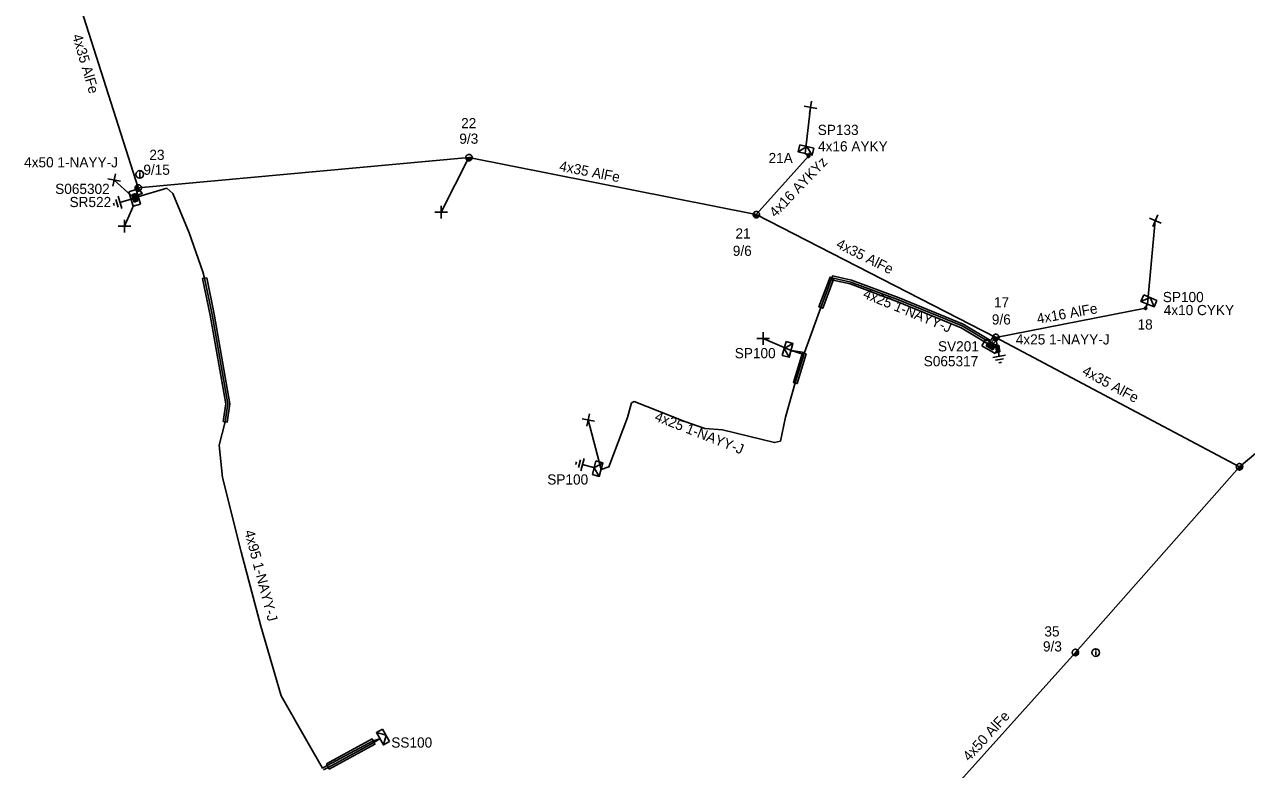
# Model space of a CAD drawing. Extents: x -748492 to -735633, y -1146251 to -1139940.
# Drawn here: x -745823 to -745702.9, y -1143676.6 to -1143603.4 of the extents above; entities that cross this region are included whole.
import ezdxf

# ---------------------------------------------------------------- set-up
doc = ezdxf.new("R2010")
doc.units = 0
for name, color, linetype in [('Vrstva 1', 7, 'Continuous'), ('Vrstva 10', 7, 'Continuous'), ('Vrstva 12', 7, 'Continuous'), ('Vrstva 13', 7, 'Continuous'), ('Vrstva 14', 7, 'Continuous'), ('Vrstva 15', 7, 'Continuous'), ('Vrstva 16', 7, 'Continuous'), ('Vrstva 2', 7, 'Continuous'), ('Vrstva 20', 7, 'Continuous'), ('Vrstva 28', 7, 'Continuous'), ('Vrstva 29', 7, 'Continuous'), ('Vrstva 30', 7, 'Continuous'), ('Vrstva 31', 7, 'Continuous'), ('Vrstva 33', 7, 'Continuous'), ('Vrstva 34', 7, 'Continuous'), ('Vrstva 36', 7, 'Continuous'), ('Vrstva 5', 7, 'Continuous'), ('Vrstva 52', 7, 'Continuous'), ('Vrstva 53', 7, 'Continuous'), ('Vrstva 54', 7, 'Continuous'), ('Vrstva 59', 7, 'Continuous'), ('Vrstva 6', 7, 'Continuous'), ('Vrstva 8', 7, 'Continuous'), ('Vrstva 9', 7, 'Continuous')]:
    doc.layers.add(name, color=color, linetype=linetype)

# ---------------------------------------------------------------- blocks, each defined once
blk = doc.blocks.new('NN440')
at = {"layer": 'Vrstva 2'}
for points in [[(0.63, 0), (0.63, 0.06), (0.62, 0.13), (0.6, 0.19), (0.58, 0.25), (0.55, 0.31), (0.51, 0.37), (0.47, 0.42), (0.42, 0.46), (0.37, 0.51), (0.32, 0.54), (0.26, 0.57), (0.2, 0.59), (0.13, 0.61), (0.07, 0.62), (0, 0.63), (-0.06, 0.62), (-0.13, 0.61), (-0.19, 0.59), (-0.26, 0.57), (-0.31, 0.54), (-0.37, 0.51), (-0.42, 0.46), (-0.47, 0.42), (-0.51, 0.37), (-0.54, 0.31), (-0.57, 0.25), (-0.6, 0.19), (-0.62, 0.13), (-0.63, 0.06), (-0.63, 0), (-0.63, -0.07), (-0.62, -0.14), (-0.6, -0.2), (-0.57, -0.26), (-0.54, -0.32), (-0.51, -0.37), (-0.47, -0.43), (-0.42, -0.47), (-0.37, -0.51), (-0.31, -0.55), (-0.26, -0.58), (-0.19, -0.6), (-0.13, -0.62), (-0.06, -0.63), (0, -0.63), (0.07, -0.63), (0.13, -0.62), (0.2, -0.6), (0.26, -0.58), (0.32, -0.55), (0.37, -0.51), (0.42, -0.47), (0.47, -0.43), (0.51, -0.37), (0.55, -0.32), (0.58, -0.26), (0.6, -0.2), (0.62, -0.14), (0.63, -0.07), (0.63, 0)], [(-0.63, 0), (0.63, 0)], [(-0.6, -0.18), (0.57, -0.18)], [(-0.51, -0.32), (0.5, -0.32)], [(-0.37, -0.47), (0.35, -0.47)]]:
    blk.add_lwpolyline(points, dxfattribs=at)
blk = doc.blocks.new('NN770')
at = {"layer": 'Vrstva 10'}
for p, q in [((0, 0.19), (0, 0.26)), ((0, -0.28), (0, 0.11))]:
    blk.add_line(p, q, dxfattribs=at)
blk.add_circle((0, -0.01), 0.375, dxfattribs=at)
blk = doc.blocks.new('NN800')
at = {"layer": 'Vrstva 1'}
for points in [[(-0.44, 0.44), (0.44, -0.44)], [(-0.44, -0.44), (0.44, 0.44)]]:
    blk.add_lwpolyline(points, dxfattribs=at)
blk = doc.blocks.new('NN820')
at = {"layer": 'Vrstva 13'}
for points in [[(0, 0), (0, -1.05)], [(-0.16, -0.81), (0.16, -0.81)], [(-0.16, -1.47), (-0.16, -0.81)], [(0, -1.05), (-0.06, -0.93)], [(0, -1.05), (0.06, -0.93)], [(0.16, -0.81), (0.16, -1.47)], [(0.16, -1.47), (-0.16, -1.47)], [(0, -1.47), (0, -1.87)]]:
    blk.add_lwpolyline(points, dxfattribs=at)
blk = doc.blocks.new('NN620')
at = {"layer": 'Vrstva 8'}
for points in [[(0.75, 0), (-0.75, 0)], [(-0.75, 0), (-0.75, -0.75)], [(0.75, -0.75), (0.75, 0)], [(-0.75, -0.75), (0.75, -0.75)], [(0.37, -0.18), (-0.38, -0.18)], [(-0.38, -0.18), (-0.38, -0.56)], [(-0.38, -0.56), (0.37, -0.56)], [(0.32, -0.23), (-0.33, -0.23)], [(-0.33, -0.23), (-0.33, -0.51)], [(-0.33, -0.51), (0.32, -0.51)], [(0.27, -0.27), (-0.28, -0.27)], [(-0.28, -0.27), (-0.28, -0.46)], [(-0.28, -0.46), (0.27, -0.46)], [(0.23, -0.32), (-0.23, -0.32)], [(-0.23, -0.32), (-0.23, -0.42)], [(-0.23, -0.42), (0.23, -0.42)], [(-0.19, -0.37), (0.19, -0.37)], [(0.23, -0.42), (0.23, -0.32)], [(0.27, -0.46), (0.27, -0.27)], [(0.32, -0.51), (0.32, -0.23)], [(0.37, -0.56), (0.37, -0.18)]]:
    blk.add_lwpolyline(points, dxfattribs=at)
blk = doc.blocks.new('NN630')
at = {"layer": 'Vrstva 9'}
for points in [[(0, -0.7), (-0.7, 0)], [(-0.7, -0.7), (-0.7, 0), (0.7, 0), (0.7, -0.7)], [(-0.7, -0.7), (0.7, -0.7)], [(0, -0.7), (0.7, 0)]]:
    blk.add_lwpolyline(points, dxfattribs=at)
blk = doc.blocks.new('NN810')
at = {"layer": 'Vrstva 14'}
for points in [[(0, -0.64), (0, -1.89)], [(0.63, -1.89), (-0.62, -1.89)], [(0.39, -2.2), (-0.4, -2.2)], [(0, -2.52), (-0.12, -2.52)], [(0.14, -2.52), (0, -2.52)]]:
    blk.add_lwpolyline(points, dxfattribs=at)
blk = doc.blocks.new('NN500')
at = {"layer": 'Vrstva 2'}
for points in [[(0, -0.24), (0.02, -0.23), (0.05, -0.23), (0.07, -0.22), (0.09, -0.22), (0.12, -0.2), (0.14, -0.19), (0.16, -0.18), (0.17, -0.16), (0.19, -0.14), (0.2, -0.12), (0.21, -0.1), (0.22, -0.07), (0.23, -0.05), (0.23, -0.02), (0.23, 0), (0.23, 0.02), (0.23, 0.05), (0.22, 0.07), (0.21, 0.1), (0.2, 0.12), (0.19, 0.14), (0.17, 0.16), (0.16, 0.17), (0.14, 0.19), (0.12, 0.2), (0.09, 0.21), (0.07, 0.22), (0.05, 0.23), (0.02, 0.23), (0, 0.23), (-0.03, 0.23), (-0.05, 0.23), (-0.07, 0.22), (-0.1, 0.21), (-0.12, 0.2), (-0.14, 0.19), (-0.16, 0.17), (-0.18, 0.16), (-0.19, 0.14), (-0.2, 0.12), (-0.22, 0.1), (-0.22, 0.07), (-0.23, 0.05), (-0.23, 0.02), (-0.24, 0), (-0.23, -0.02), (-0.23, -0.05), (-0.22, -0.07), (-0.22, -0.1), (-0.2, -0.12), (-0.19, -0.14), (-0.18, -0.16), (-0.16, -0.18), (-0.14, -0.19), (-0.12, -0.2), (-0.1, -0.22), (-0.07, -0.22), (-0.05, -0.23), (-0.03, -0.23), (0, -0.24)], [(0, -0.24), (0.02, -0.23), (0.05, -0.23), (0.07, -0.22), (0.09, -0.22), (0.12, -0.2), (0.14, -0.19), (0.16, -0.18), (0.17, -0.16), (0.19, -0.14), (0.2, -0.12), (0.21, -0.1), (0.22, -0.07), (0.23, -0.05), (0.23, -0.02), (0.23, 0), (0.23, 0.02), (0.23, 0.05), (0.22, 0.07), (0.21, 0.1), (0.2, 0.12), (0.19, 0.14), (0.17, 0.16), (0.16, 0.17), (0.14, 0.19), (0.12, 0.2), (0.09, 0.21), (0.07, 0.22), (0.05, 0.23), (0.02, 0.23), (0, 0.23), (-0.03, 0.23), (-0.05, 0.23), (-0.07, 0.22), (-0.1, 0.21), (-0.12, 0.2), (-0.14, 0.19), (-0.16, 0.17), (-0.18, 0.16), (-0.19, 0.14), (-0.2, 0.12), (-0.22, 0.1), (-0.22, 0.07), (-0.23, 0.05), (-0.23, 0.02), (-0.24, 0), (-0.23, -0.02), (-0.23, -0.05), (-0.22, -0.07), (-0.22, -0.1), (-0.2, -0.12), (-0.19, -0.14), (-0.18, -0.16), (-0.16, -0.18), (-0.14, -0.19), (-0.12, -0.2), (-0.1, -0.22), (-0.07, -0.22), (-0.05, -0.23), (-0.03, -0.23), (0, -0.24)], [(0, -0.21), (0.02, -0.2), (0.04, -0.2), (0.06, -0.2), (0.08, -0.19), (0.1, -0.18), (0.12, -0.17), (0.14, -0.15), (0.15, -0.14), (0.16, -0.12), (0.18, -0.1), (0.19, -0.08), (0.19, -0.06), (0.2, -0.04), (0.2, -0.02), (0.2, 0), (0.2, 0.02), (0.2, 0.04), (0.19, 0.06), (0.19, 0.08), (0.18, 0.1), (0.16, 0.12), (0.15, 0.14), (0.14, 0.15), (0.12, 0.17), (0.1, 0.18), (0.08, 0.19), (0.06, 0.19), (0.04, 0.2), (0.02, 0.2), (0, 0.2), (-0.02, 0.2), (-0.04, 0.2), (-0.06, 0.19), (-0.08, 0.19), (-0.1, 0.18), (-0.12, 0.17), (-0.14, 0.15), (-0.15, 0.14), (-0.17, 0.12), (-0.18, 0.1), (-0.19, 0.08), (-0.2, 0.06), (-0.2, 0.04), (-0.21, 0.02), (-0.21, 0), (-0.21, -0.02), (-0.2, -0.04), (-0.2, -0.06), (-0.19, -0.08), (-0.18, -0.1), (-0.17, -0.12), (-0.15, -0.14), (-0.14, -0.15), (-0.12, -0.17), (-0.1, -0.18), (-0.08, -0.19), (-0.06, -0.2), (-0.04, -0.2), (-0.02, -0.2), (0, -0.21)], [(0, -0.18), (0.02, -0.18), (0.04, -0.17), (0.05, -0.17), (0.07, -0.16), (0.09, -0.15), (0.1, -0.14), (0.12, -0.13), (0.13, -0.12), (0.14, -0.1), (0.15, -0.09), (0.16, -0.07), (0.17, -0.05), (0.17, -0.04), (0.17, -0.02), (0.17, 0), (0.17, 0.02), (0.17, 0.04), (0.17, 0.05), (0.16, 0.07), (0.15, 0.09), (0.14, 0.1), (0.13, 0.12), (0.12, 0.13), (0.1, 0.14), (0.09, 0.15), (0.07, 0.16), (0.05, 0.17), (0.04, 0.17), (0.02, 0.17), (0, 0.18), (-0.02, 0.17), (-0.04, 0.17), (-0.06, 0.17), (-0.07, 0.16), (-0.09, 0.15), (-0.1, 0.14), (-0.12, 0.13), (-0.13, 0.12), (-0.14, 0.1), (-0.15, 0.09), (-0.16, 0.07), (-0.17, 0.05), (-0.17, 0.04), (-0.18, 0.02), (-0.18, 0), (-0.18, -0.02), (-0.17, -0.04), (-0.17, -0.05), (-0.16, -0.07), (-0.15, -0.09), (-0.14, -0.1), (-0.13, -0.12), (-0.12, -0.13), (-0.1, -0.14), (-0.09, -0.15), (-0.07, -0.16), (-0.06, -0.17), (-0.04, -0.17), (-0.02, -0.18), (0, -0.18)], [(0, -0.15), (0.01, -0.15), (0.03, -0.14), (0.04, -0.14), (0.06, -0.13), (0.07, -0.13), (0.08, -0.12), (0.1, -0.11), (0.11, -0.1), (0.12, -0.09), (0.13, -0.07), (0.13, -0.06), (0.14, -0.05), (0.14, -0.03), (0.14, -0.02), (0.14, 0), (0.14, 0.01), (0.14, 0.03), (0.14, 0.04), (0.13, 0.06), (0.13, 0.07), (0.12, 0.09), (0.11, 0.1), (0.1, 0.11), (0.08, 0.12), (0.07, 0.13), (0.06, 0.13), (0.04, 0.14), (0.03, 0.14), (0.01, 0.14), (0, 0.15), (-0.02, 0.14), (-0.03, 0.14), (-0.05, 0.14), (-0.06, 0.13), (-0.07, 0.13), (-0.09, 0.12), (-0.1, 0.11), (-0.11, 0.1), (-0.12, 0.09), (-0.13, 0.07), (-0.13, 0.06), (-0.14, 0.04), (-0.14, 0.03), (-0.15, 0.01), (-0.15, 0), (-0.15, -0.02), (-0.14, -0.03), (-0.14, -0.05), (-0.13, -0.06), (-0.13, -0.07), (-0.12, -0.09), (-0.11, -0.1), (-0.1, -0.11), (-0.09, -0.12), (-0.07, -0.13), (-0.06, -0.13), (-0.05, -0.14), (-0.03, -0.14), (-0.02, -0.15), (0, -0.15)], [(0, -0.12), (0.01, -0.12), (0.02, -0.11), (0.03, -0.11), (0.05, -0.11), (0.06, -0.1), (0.07, -0.09), (0.08, -0.09), (0.09, -0.08), (0.09, -0.07), (0.1, -0.06), (0.11, -0.05), (0.11, -0.04), (0.11, -0.02), (0.11, -0.01), (0.12, 0), (0.11, 0.01), (0.11, 0.02), (0.11, 0.04), (0.11, 0.05), (0.1, 0.06), (0.09, 0.07), (0.09, 0.08), (0.08, 0.09), (0.07, 0.09), (0.06, 0.1), (0.05, 0.11), (0.03, 0.11), (0.02, 0.11), (0.01, 0.12), (0, 0.12), (-0.01, 0.12), (-0.03, 0.11), (-0.04, 0.11), (-0.05, 0.11), (-0.06, 0.1), (-0.07, 0.09), (-0.08, 0.09), (-0.09, 0.08), (-0.1, 0.07), (-0.1, 0.06), (-0.11, 0.05), (-0.11, 0.04), (-0.12, 0.02), (-0.12, 0.01), (-0.12, 0), (-0.12, -0.01), (-0.12, -0.02), (-0.11, -0.04), (-0.11, -0.05), (-0.1, -0.06), (-0.1, -0.07), (-0.09, -0.08), (-0.08, -0.09), (-0.07, -0.09), (-0.06, -0.1), (-0.05, -0.11), (-0.04, -0.11), (-0.03, -0.11), (-0.01, -0.12), (0, -0.12)], [(0, -0.09), (0.01, -0.09), (0.02, -0.09), (0.03, -0.08), (0.03, -0.08), (0.04, -0.08), (0.05, -0.07), (0.06, -0.07), (0.06, -0.06), (0.07, -0.05), (0.07, -0.04), (0.08, -0.04), (0.08, -0.03), (0.08, -0.02), (0.09, -0.01), (0.09, 0), (0.09, 0.01), (0.08, 0.02), (0.08, 0.03), (0.08, 0.03), (0.07, 0.04), (0.07, 0.05), (0.06, 0.06), (0.06, 0.06), (0.05, 0.07), (0.04, 0.07), (0.03, 0.08), (0.03, 0.08), (0.02, 0.08), (0.01, 0.09), (0, 0.09), (-0.01, 0.09), (-0.02, 0.08), (-0.03, 0.08), (-0.04, 0.08), (-0.04, 0.07), (-0.05, 0.07), (-0.06, 0.06), (-0.07, 0.06), (-0.07, 0.05), (-0.08, 0.04), (-0.08, 0.03), (-0.08, 0.03), (-0.09, 0.02), (-0.09, 0.01), (-0.09, 0), (-0.09, -0.01), (-0.09, -0.02), (-0.08, -0.03), (-0.08, -0.04), (-0.08, -0.04), (-0.07, -0.05), (-0.07, -0.06), (-0.06, -0.07), (-0.05, -0.07), (-0.04, -0.08), (-0.04, -0.08), (-0.03, -0.08), (-0.02, -0.09), (-0.01, -0.09), (0, -0.09)], [(0, -0.06), (0, -0.06), (0.01, -0.06), (0.02, -0.05), (0.02, -0.05), (0.03, -0.05), (0.03, -0.05), (0.04, -0.04), (0.04, -0.04), (0.05, -0.03), (0.05, -0.03), (0.05, -0.02), (0.05, -0.02), (0.05, -0.01), (0.06, -0.01), (0.06, 0), (0.06, 0.01), (0.05, 0.01), (0.05, 0.02), (0.05, 0.02), (0.05, 0.03), (0.05, 0.03), (0.04, 0.04), (0.04, 0.04), (0.03, 0.05), (0.03, 0.05), (0.02, 0.05), (0.02, 0.05), (0.01, 0.06), (0, 0.06), (0, 0.06), (-0.01, 0.06), (-0.01, 0.06), (-0.02, 0.05), (-0.02, 0.05), (-0.03, 0.05), (-0.03, 0.05), (-0.04, 0.04), (-0.04, 0.04), (-0.05, 0.03), (-0.05, 0.03), (-0.05, 0.02), (-0.06, 0.02), (-0.06, 0.01), (-0.06, 0.01), (-0.06, 0), (-0.06, -0.01), (-0.06, -0.01), (-0.06, -0.02), (-0.05, -0.02), (-0.05, -0.03), (-0.05, -0.03), (-0.04, -0.04), (-0.04, -0.04), (-0.03, -0.05), (-0.03, -0.05), (-0.02, -0.05), (-0.02, -0.05), (-0.01, -0.06), (-0.01, -0.06), (0, -0.06)], [(0, -0.03), (0, -0.03), (0, -0.03), (0.01, -0.03), (0.01, -0.03), (0.01, -0.02), (0.02, -0.02), (0.02, -0.02), (0.02, -0.02), (0.02, -0.02), (0.02, -0.01), (0.02, -0.01), (0.03, -0.01), (0.03, -0.01), (0.03, 0), (0.03, 0), (0.03, 0), (0.03, 0.01), (0.03, 0.01), (0.02, 0.01), (0.02, 0.01), (0.02, 0.02), (0.02, 0.02), (0.02, 0.02), (0.02, 0.02), (0.01, 0.02), (0.01, 0.02), (0.01, 0.03), (0, 0.03), (0, 0.03), (0, 0.03), (0, 0.03), (-0.01, 0.03), (-0.01, 0.03), (-0.01, 0.02), (-0.02, 0.02), (-0.02, 0.02), (-0.02, 0.02), (-0.02, 0.02), (-0.02, 0.02), (-0.03, 0.01), (-0.03, 0.01), (-0.03, 0.01), (-0.03, 0.01), (-0.03, 0), (-0.03, 0), (-0.03, 0), (-0.03, -0.01), (-0.03, -0.01), (-0.03, -0.01), (-0.03, -0.01), (-0.02, -0.02), (-0.02, -0.02), (-0.02, -0.02), (-0.02, -0.02), (-0.02, -0.02), (-0.01, -0.03), (-0.01, -0.03), (-0.01, -0.03), (0, -0.03), (0, -0.03)], [(0.23, 0), (0.7, 0)]]:
    blk.add_lwpolyline(points, dxfattribs=at)

msp = doc.modelspace()

# ---------------------------------------------------------------- linework, layer by layer
at = {"layer": 'Vrstva 1'}
for points in [[(-745811.79, -1143619.48), (-745821.98, -1143587.51)], [(-745751.09, -1143622.1), (-745779.31, -1143616.5), (-745811.79, -1143619.48)], [(-745727.57, -1143634.15), (-745751.09, -1143622.1)], [(-745678.33, -1143625.83), (-745703.64, -1143646.86)], [(-745727.57, -1143634.15), (-745712.87, -1143631.29)], [(-745703.64, -1143646.86), (-745727.57, -1143634.15)], [(-745703.64, -1143646.86), (-745719.75, -1143665.09), (-745735.66, -1143682.8), (-745743.19, -1143708.05)]]:
    msp.add_lwpolyline(points, dxfattribs=at)
at = {"layer": 'Vrstva 20'}
for points in [[(-745805.07, -1143628.29), (-745804.33, -1143631.88), (-745802.79, -1143640.67), (-745803.05, -1143642.47), (-745803.45, -1143642.41), (-745803.19, -1143640.67), (-745804.73, -1143631.96), (-745805.47, -1143628.37)], [(-745743.47, -1143628.38), (-745744.57, -1143631.29), (-745744.95, -1143631.15), (-745743.85, -1143628.24)], [(-745727.42, -1143634.28), (-745728.02, -1143634.98), (-745730.97, -1143633.2), (-745737.2, -1143630.65), (-745741.87, -1143628.91), (-745743.7, -1143628.51), (-745743.62, -1143628.11), (-745741.75, -1143628.53), (-745737.06, -1143630.27), (-745730.79, -1143632.84), (-745728.1, -1143634.46), (-745727.72, -1143634.02)], [(-745746.19, -1143635.78), (-745747.07, -1143638.69), (-745747.45, -1143638.57), (-745746.57, -1143635.66)], [(-745793.32, -1143676.02), (-745788.83, -1143673.58), (-745788.55, -1143674.1), (-745793.04, -1143676.54)]]:
    msp.add_lwpolyline(points, close=True, dxfattribs=at)
at = {"layer": 'Vrstva 5'}
for points in [[(-745811.79, -1143619.48), (-745811.4, -1143620.01), (-745811.85, -1143620.19)], [(-745811.82, -1143620.35), (-745808.99, -1143619.51), (-745808.38, -1143620.02), (-745806.79, -1143623.9), (-745805.45, -1143627.7), (-745805.27, -1143628.33), (-745804.53, -1143631.92), (-745802.99, -1143640.67), (-745803.25, -1143642.44), (-745803.86, -1143644.73), (-745803.52, -1143647.91), (-745801.68, -1143655.2), (-745799.76, -1143662.52), (-745797.77, -1143669.35), (-745795.1, -1143673.99), (-745793.69, -1143676.44), (-745793.23, -1143676.19), (-745788.73, -1143673.75), (-745788.06, -1143673.56), (-745788.65, -1143673.93), (-745793.13, -1143676.37), (-745793.59, -1143676.62)], [(-745728.43, -1143634.5), (-745730.88, -1143633.02), (-745737.13, -1143630.46), (-745741.81, -1143628.72), (-745743.66, -1143628.31), (-745744.76, -1143631.22), (-745746.35, -1143635.62), (-745747.68, -1143635.43), (-745746.41, -1143635.82), (-745747.26, -1143638.63), (-745748.22, -1143641.98), (-745748.73, -1143644.33), (-745749.29, -1143644.48), (-745754.41, -1143643.24), (-745756.15, -1143643.09), (-745758.12, -1143642.41), (-745763.1, -1143640.46), (-745763.35, -1143640.59), (-745763.73, -1143642.02), (-745765.56, -1143646.87), (-745766.34, -1143647.13)], [(-745727.57, -1143634.15), (-745728.06, -1143634.72)]]:
    msp.add_lwpolyline(points, dxfattribs=at)
at = {"layer": 'Vrstva 52'}
for points in [[(-745751.09, -1143622.1), (-745745.96, -1143616.36)], [(-745745.96, -1143616.36), (-745746.3, -1143616.1)], [(-745712.87, -1143631.29), (-745712.67, -1143630.89)]]:
    msp.add_lwpolyline(points, dxfattribs=at)
at = {"layer": 'Vrstva 59'}
for points in [[(-745746.3, -1143616.1), (-745745.77, -1143611.58)], [(-745779.31, -1143616.5), (-745782.04, -1143621.86)], [(-745812.5, -1143620.21), (-745814.16, -1143618.7)], [(-745812.21, -1143621.13), (-745813.14, -1143623.22)], [(-745712.67, -1143630.89), (-745711.91, -1143622.68)], [(-745747.68, -1143635.43), (-745750.43, -1143634.26)], [(-745766.34, -1143647.13), (-745767.6, -1143642.26)]]:
    msp.add_lwpolyline(points, dxfattribs=at)

# ---------------------------------------------------------------- block references
at = {"layer": 'Vrstva 13'}
for name, p, xscale, yscale, rotation in [('NN440', (-745779.31, -1143616.5), 0.5000000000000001, 0.5, 5.815644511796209), ('NN500', (-745745.96, -1143616.36), 0.5, 0.5, 75.76299998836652), ('NN440', (-745811.79, -1143619.48), 0.5, 0.5, -74.03899169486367), ('NN440', (-745751.09, -1143622.1), 0.49999999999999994, 0.5000000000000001, -19.92358890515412), ('NN500', (-745712.87, -1143631.29), 0.5, 0.5, 67.37999991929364), ('NN440', (-745727.57, -1143634.15), 0.5, 0.5000000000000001, 9.750149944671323), ('NN440', (-745703.64, -1143646.86), 0.5000000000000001, 0.4999999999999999, 39.88677223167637), ('NN440', (-745719.75, -1143665.09), 0.5, 0.49999999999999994, 46.95527220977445)]:
    msp.add_blockref(name, p, dxfattribs=dict(at, xscale=xscale, yscale=yscale, rotation=rotation))
at = {"layer": 'Vrstva 15'}
for p, rotation in [((-745811.78, -1143620.35), -73.23443174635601), ((-745727.57, -1143634.15), 9.750149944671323), ((-745766.34, -1143647.13), -104.85469889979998)]:
    msp.add_blockref('NN810', p, dxfattribs=dict(at, rotation=rotation))
at = {"layer": 'Vrstva 16', "rotation": 9.750149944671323}
msp.add_blockref('NN820', (-745727.57, -1143634.15), dxfattribs=at)
at = {"layer": 'Vrstva 28'}
for p, rotation in [((-745811.78, -1143620.35), -73.23443174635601), ((-745727.91, -1143634.7), -30.33733489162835)]:
    msp.add_blockref('NN620', p, dxfattribs=dict(at, rotation=rotation))
at = {"layer": 'Vrstva 31'}
for p, rotation in [((-745746.3, -1143616.1), 166.5027306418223), ((-745712.67, -1143630.89), 156.8879777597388), ((-745747.68, -1143635.43), -105.25511875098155), ((-745766.34, -1143647.13), -104.85469889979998), ((-745788.06, -1143673.56), 119.24882635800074)]:
    msp.add_blockref('NN630', p, dxfattribs=dict(at, rotation=rotation))
at = {"layer": 'Vrstva 34'}
for p, rotation in [((-745745.77, -1143611.58), -145.58310272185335), ((-745814.16, -1143618.7), -55.97627220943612), ((-745782.04, -1143621.86), 45), ((-745813.14, -1143623.22), 45), ((-745711.91, -1143622.68), -157.90211673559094), ((-745750.43, -1143634.26), 45), ((-745767.6, -1143642.26), -146.65313885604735)]:
    msp.add_blockref('NN800', p, dxfattribs=dict(at, rotation=rotation))
at = {"layer": 'Vrstva 36'}
for p in [(-745811.64, -1143618.14), (-745717.75, -1143665.09)]:
    msp.add_blockref('NN770', p, dxfattribs=at)

# ---------------------------------------------------------------- texts
at = {"layer": 'Vrstva 12'}
for s, p in [('9/3', (-745780.26, -1143615.14)), ('9/15', (-745811.29, -1143618.19)), ('9/6', (-745753.4, -1143626.15)), ('9/6', (-745727.96, -1143632.89)), ('9/3', (-745722.94, -1143664.99))]:
    msp.add_text(s, height=1, dxfattribs=at).set_placement(p)
at = {"layer": 'Vrstva 14'}
for s, p in [('22', (-745780.08, -1143613.62)), ('23', (-745810.7, -1143616.73)), ('21A', (-745749.89, -1143617.04)), ('21', (-745753.14, -1143624.45)), ('17', (-745727.75, -1143631.21)), ('18', (-745713.65, -1143633.38)), ('35', (-745722.8, -1143663.52))]:
    msp.add_text(s, height=1, dxfattribs=at).set_placement(p)
at = {"layer": 'Vrstva 2'}
for s, rotation, p in [('4x35 AlFe', 286.403, (-745818.29, -1143604.53)), ('4x35 AlFe', 349.097, (-745770.5, -1143617.79)), ('4x35 AlFe', 333.563, (-745743.34, -1143625.3)), ('4x16 AlFe', 10.093, (-745723.45, -1143632.82)), ('4x35 AlFe', 331.614, (-745719.18, -1143637.75)), ('4x50 AlFe', 47.703, (-745730.18, -1143675.85))]:
    msp.add_text(s, height=1, rotation=rotation, dxfattribs=at).set_placement(p)
at = {"layer": 'Vrstva 29'}
for s, p in [('S065302', (-745819.95, -1143620.07)), ('S065317', (-745734.65, -1143636.99))]:
    msp.add_text(s, height=1, dxfattribs=at).set_placement(p)
at = {"layer": 'Vrstva 30'}
for s, p in [('SR522', (-745818.54, -1143621.36)), ('SV201', (-745733.25, -1143635.53))]:
    msp.add_text(s, height=1, dxfattribs=at).set_placement(p)
at = {"layer": 'Vrstva 33'}
for s, p in [('SP133', (-745745.06, -1143614.28)), ('SP100', (-745711.17, -1143630.69)), ('SP100', (-745753.21, -1143636.2)), ('SP100', (-745771.62, -1143648.6)), ('SS100', (-745786.94, -1143674.43))]:
    msp.add_text(s, height=1, dxfattribs=at).set_placement(p)
at = {"layer": 'Vrstva 53'}
msp.add_text('4x16 AYKYz', height=1, rotation=46.265, dxfattribs=at).set_placement((-745749.21, -1143622.44))
at = {"layer": 'Vrstva 54'}
for s, rotation, p in [('4x16 AYKY', 359.969, (-745745.03, -1143615.89)), ('4x10 CYKY', 0.035, (-745711.08, -1143631.97))]:
    msp.add_text(s, height=1, rotation=rotation, dxfattribs=at).set_placement(p)
at = {"layer": 'Vrstva 6'}
for s, p in [('4x50 1-NAYY-J', (-745823, -1143617.46)), ('4x25 1-NAYY-J', (-745725.61, -1143634.85))]:
    msp.add_text(s, height=1, dxfattribs=at).set_placement(p)
for s, rotation, p in [('4x25 1-NAYY-J', 337.726, (-745740.69, -1143630.23)), ('4x25 1-NAYY-J', 338.616, (-745761.15, -1143642.3)), ('4x95 1-NAYY-J', 284.697, (-745801.38, -1143653.2))]:
    msp.add_text(s, height=1, rotation=rotation, dxfattribs=at).set_placement(p)

doc.saveas('drawing.dxf')
